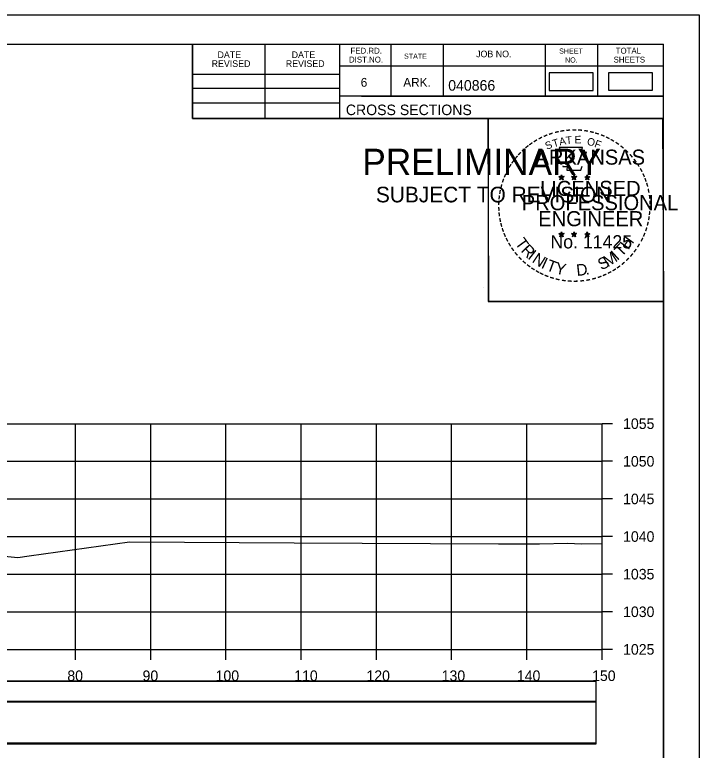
# Model space of a CAD drawing. Extents: x 1370565 to 1374448, y 301010 to 304637.
# Drawn here: x 1373440.7 to 1373531.7, y 302907.3 to 303005 of the extents above; entities that cross this region are included whole.
import ezdxf

# ---------------------------------------------------------------- set-up
doc = ezdxf.new("R2010")
doc.units = 0
for name, color, linetype in [('Default', 7, 'Continuous'), ('R_Axis', 7, 'Continuous'), ('R_Axis Annot', 7, 'Continuous'), ('R_Border', 7, 'Continuous'), ('R_Border PE', 7, 'Continuous'), ('R_Border Prem', 7, 'Continuous'), ('R_Drive', 7, 'Continuous'), ('R_Exist Surface', 7, 'Continuous'), ('R_Grid', 7, 'Continuous'), ('R_No Plot', 7, 'Continuous')]:
    doc.layers.add(name, color=color, linetype=linetype)

msp = doc.modelspace()

# ---------------------------------------------------------------- linework, layer by layer
at = {"layer": 'Default'}
for points in [[(1373511.808, 302994.967), (1373517.641, 302994.967), (1373517.641, 302997.277), (1373511.808, 302997.277)], [(1373219.605, 302913.703), (1373518.024, 302913.703), (1373518.024, 302916.409), (1373219.605, 302916.409)], [(1373219.605, 302908.125), (1373518.024, 302908.125), (1373518.024, 302913.648), (1373219.605, 302913.648)]]:
    msp.add_lwpolyline(points, close=True, dxfattribs=at)
at = {"layer": 'R_Axis'}
for p, q in [((1373518.814, 302920.664), (1373518.814, 302950.664)), ((1373520.214, 302950.664), (1373518.814, 302950.664)), ((1373520.214, 302945.664), (1373518.814, 302945.664)), ((1373520.214, 302940.664), (1373518.814, 302940.664)), ((1373520.214, 302935.664), (1373518.814, 302935.664)), ((1373520.214, 302930.664), (1373518.814, 302930.664)), ((1373520.214, 302925.664), (1373518.814, 302925.664)), ((1373218.814, 302920.664), (1373518.814, 302920.664)), ((1373448.814, 302919.264), (1373448.814, 302920.664)), ((1373458.814, 302919.264), (1373458.814, 302920.664)), ((1373468.814, 302919.264), (1373468.814, 302920.664)), ((1373478.814, 302919.264), (1373478.814, 302920.664)), ((1373488.814, 302919.264), (1373488.814, 302920.664)), ((1373498.814, 302919.264), (1373498.814, 302920.664)), ((1373508.814, 302919.264), (1373508.814, 302920.664)), ((1373518.814, 302919.264), (1373518.814, 302920.664)), ((1373520.214, 302920.664), (1373518.814, 302920.664))]:
    msp.add_line(p, q, dxfattribs=at)
at = {"layer": 'R_Border'}
for p, q in [((1373210.814, 303001.124), (1373526.994, 303001.124)), ((1373464.354, 302991.244), (1373464.354, 303001.124)), ((1373474.034, 302991.244), (1373474.034, 303001.124)), ((1373483.894, 303001.124), (1373483.894, 302991.244)), ((1373490.734, 303001.124), (1373490.734, 302994.184)), ((1373497.674, 303001.124), (1373497.674, 302994.184)), ((1373511.254, 303001.124), (1373511.254, 302994.184)), ((1373518.194, 303001.124), (1373518.194, 302994.184)), ((1373526.994, 302795.664), (1373526.994, 303001.124)), ((1373526.994, 302998.184), (1373483.894, 302998.184)), ((1373526.994, 302998.204), (1373526.994, 302998.204)), ((1373464.354, 302997.104), (1373483.894, 302997.104)), ((1373464.354, 302995.244), (1373483.894, 302995.244)), ((1373526.994, 302994.184), (1373483.894, 302994.184)), ((1373486.854, 302994.184), (1373526.994, 302994.184)), ((1373464.354, 302993.304), (1373483.894, 302993.304)), ((1373526.994, 302991.244), (1373464.354, 302991.244))]:
    msp.add_line(p, q, dxfattribs=at)
at = {"layer": 'R_Border PE'}
for p, q in [((1373513.079, 302983.499), (1373513.428, 302983.388)), ((1373513.079, 302983.499), (1373513.332, 302983.454)), ((1373513.079, 302983.499), (1373513.316, 302983.377)), ((1373513.212, 302983.091), (1373513.428, 302983.388)), ((1373513.212, 302983.091), (1373513.338, 302983.335)), ((1373513.212, 302983.091), (1373513.426, 302983.308)), ((1373513.428, 302983.753), (1373513.387, 302983.501)), ((1373513.641, 302983.091), (1373513.426, 302983.305)), ((1373513.428, 302983.388), (1373513.428, 302983.753)), ((1373513.428, 302983.753), (1373513.477, 302983.503)), ((1373513.775, 302983.499), (1373513.428, 302983.388)), ((1373513.641, 302983.091), (1373513.428, 302983.388)), ((1373513.775, 302983.499), (1373513.489, 302983.45)), ((1373513.641, 302983.091), (1373513.504, 302983.382)), ((1373513.775, 302983.499), (1373513.571, 302983.397)), ((1373514.749, 302983.499), (1373515.098, 302983.388)), ((1373514.749, 302983.499), (1373515.002, 302983.454)), ((1373514.749, 302983.499), (1373514.986, 302983.377)), ((1373514.882, 302983.091), (1373515.098, 302983.388)), ((1373514.882, 302983.091), (1373515.008, 302983.335)), ((1373514.882, 302983.091), (1373515.096, 302983.308)), ((1373515.098, 302983.753), (1373515.057, 302983.501)), ((1373515.311, 302983.091), (1373515.096, 302983.305)), ((1373515.098, 302983.388), (1373515.098, 302983.753)), ((1373515.098, 302983.753), (1373515.147, 302983.503)), ((1373515.445, 302983.499), (1373515.098, 302983.388)), ((1373515.311, 302983.091), (1373515.098, 302983.388)), ((1373515.445, 302983.499), (1373515.159, 302983.45)), ((1373515.311, 302983.091), (1373515.174, 302983.382)), ((1373515.445, 302983.499), (1373515.241, 302983.397)), ((1373516.513, 302983.487), (1373516.862, 302983.376)), ((1373516.513, 302983.487), (1373516.766, 302983.442)), ((1373516.513, 302983.487), (1373516.75, 302983.365)), ((1373516.646, 302983.079), (1373516.862, 302983.376)), ((1373516.646, 302983.079), (1373516.772, 302983.323)), ((1373516.646, 302983.079), (1373516.86, 302983.296)), ((1373516.862, 302983.741), (1373516.821, 302983.489)), ((1373517.075, 302983.079), (1373516.86, 302983.293)), ((1373516.862, 302983.376), (1373516.862, 302983.741)), ((1373516.862, 302983.741), (1373516.911, 302983.491)), ((1373517.209, 302983.487), (1373516.862, 302983.376)), ((1373517.075, 302983.079), (1373516.862, 302983.376)), ((1373517.209, 302983.487), (1373516.923, 302983.438)), ((1373517.075, 302983.079), (1373516.938, 302983.37)), ((1373517.209, 302983.487), (1373517.005, 302983.385)), ((1373513.075, 302975.926), (1373513.424, 302975.815)), ((1373513.075, 302975.926), (1373513.328, 302975.881)), ((1373513.075, 302975.926), (1373513.312, 302975.804)), ((1373513.208, 302975.518), (1373513.424, 302975.815)), ((1373513.208, 302975.518), (1373513.334, 302975.762)), ((1373513.208, 302975.518), (1373513.422, 302975.735)), ((1373513.424, 302976.18), (1373513.383, 302975.928)), ((1373513.637, 302975.518), (1373513.422, 302975.732)), ((1373513.424, 302975.815), (1373513.424, 302976.18)), ((1373513.424, 302976.18), (1373513.473, 302975.93)), ((1373513.771, 302975.926), (1373513.424, 302975.815)), ((1373513.637, 302975.518), (1373513.424, 302975.815)), ((1373513.771, 302975.926), (1373513.485, 302975.877)), ((1373513.637, 302975.518), (1373513.5, 302975.809)), ((1373513.771, 302975.926), (1373513.567, 302975.824)), ((1373514.744, 302975.926), (1373515.093, 302975.815)), ((1373514.744, 302975.926), (1373514.997, 302975.881)), ((1373514.744, 302975.926), (1373514.981, 302975.804)), ((1373514.877, 302975.518), (1373515.093, 302975.815)), ((1373514.877, 302975.518), (1373515.003, 302975.762)), ((1373514.877, 302975.518), (1373515.091, 302975.735)), ((1373515.093, 302976.18), (1373515.052, 302975.928)), ((1373515.306, 302975.518), (1373515.091, 302975.732)), ((1373515.093, 302975.815), (1373515.093, 302976.18)), ((1373515.093, 302976.18), (1373515.142, 302975.93)), ((1373515.44, 302975.926), (1373515.093, 302975.815)), ((1373515.306, 302975.518), (1373515.093, 302975.815)), ((1373515.44, 302975.926), (1373515.154, 302975.877)), ((1373515.306, 302975.518), (1373515.169, 302975.809)), ((1373515.44, 302975.926), (1373515.236, 302975.824)), ((1373516.511, 302975.916), (1373516.86, 302975.805)), ((1373516.511, 302975.916), (1373516.764, 302975.871)), ((1373516.511, 302975.916), (1373516.748, 302975.794)), ((1373516.644, 302975.508), (1373516.86, 302975.805)), ((1373516.644, 302975.508), (1373516.77, 302975.752)), ((1373516.644, 302975.508), (1373516.858, 302975.725)), ((1373516.86, 302976.17), (1373516.819, 302975.918)), ((1373517.073, 302975.508), (1373516.858, 302975.722)), ((1373516.86, 302975.805), (1373516.86, 302976.17)), ((1373516.86, 302976.17), (1373516.909, 302975.92)), ((1373517.207, 302975.916), (1373516.86, 302975.805)), ((1373517.073, 302975.508), (1373516.86, 302975.805)), ((1373517.207, 302975.916), (1373516.921, 302975.867)), ((1373517.073, 302975.508), (1373516.936, 302975.799)), ((1373517.207, 302975.916), (1373517.003, 302975.814))]:
    msp.add_line(p, q, dxfattribs=at)
for points in [[(1373513.12, 302987.377), (1373513.389, 302986.55)], [(1373516.631, 302986.455), (1373516.773, 302986.739), (1373516.088, 302986.715), (1373516.236, 302987.377), (1373513.12, 302987.377)], [(1373513.612, 302984.954), (1373513.612, 302984.867), (1373514.175, 302984.848), (1373514.121, 302984.375), (1373515.991, 302984.375), (1373516.192, 302984.911)], [(1373513.428, 302983.753), (1373513.641, 302983.091), (1373513.079, 302983.499), (1373513.775, 302983.499), (1373513.212, 302983.091), (1373513.428, 302983.753)], [(1373515.098, 302983.753), (1373515.311, 302983.091), (1373514.749, 302983.499), (1373515.445, 302983.499), (1373514.882, 302983.091), (1373515.098, 302983.753)], [(1373516.862, 302983.741), (1373517.075, 302983.079), (1373516.513, 302983.487), (1373517.209, 302983.487), (1373516.646, 302983.079), (1373516.862, 302983.741)], [(1373513.424, 302976.18), (1373513.637, 302975.518), (1373513.075, 302975.926), (1373513.771, 302975.926), (1373513.208, 302975.518), (1373513.424, 302976.18)], [(1373515.093, 302976.18), (1373515.306, 302975.518), (1373514.744, 302975.926), (1373515.44, 302975.926), (1373514.877, 302975.518), (1373515.093, 302976.18)], [(1373516.86, 302976.17), (1373517.073, 302975.508), (1373516.511, 302975.916), (1373517.207, 302975.916), (1373516.644, 302975.508), (1373516.86, 302976.17)]]:
    msp.add_lwpolyline(points, dxfattribs=at)
for centre, radius in [((1373513.427, 302983.388), 0.172), ((1373513.427, 302983.388), 0.145), ((1373513.427, 302983.388), 0.116), ((1373513.427, 302983.388), 0.0991), ((1373513.427, 302983.388), 0.0747), ((1373513.427, 302983.388), 0.0495), ((1373513.427, 302983.388), 0.0296), ((1373515.097, 302983.388), 0.172), ((1373515.097, 302983.388), 0.145), ((1373515.097, 302983.388), 0.116), ((1373515.097, 302983.388), 0.0991), ((1373515.097, 302983.388), 0.0747), ((1373515.097, 302983.388), 0.0495), ((1373515.097, 302983.388), 0.0296), ((1373516.861, 302983.376), 0.172), ((1373516.861, 302983.376), 0.145), ((1373516.861, 302983.376), 0.116), ((1373516.861, 302983.376), 0.0991), ((1373516.861, 302983.376), 0.0747), ((1373516.861, 302983.376), 0.0495), ((1373516.861, 302983.376), 0.0296), ((1373513.423, 302975.815), 0.172), ((1373513.423, 302975.815), 0.145), ((1373513.423, 302975.815), 0.116), ((1373513.423, 302975.815), 0.0991), ((1373513.423, 302975.815), 0.0747), ((1373513.423, 302975.815), 0.0495), ((1373513.423, 302975.815), 0.0296), ((1373515.092, 302975.815), 0.172), ((1373515.092, 302975.815), 0.145), ((1373515.092, 302975.815), 0.116), ((1373515.092, 302975.815), 0.0991), ((1373515.092, 302975.815), 0.0747), ((1373515.092, 302975.815), 0.0495), ((1373515.092, 302975.815), 0.0296), ((1373516.859, 302975.805), 0.172), ((1373516.859, 302975.805), 0.145), ((1373516.859, 302975.805), 0.116), ((1373516.859, 302975.805), 0.0991), ((1373516.859, 302975.805), 0.0747), ((1373516.859, 302975.805), 0.0495), ((1373516.859, 302975.805), 0.0296)]:
    msp.add_circle(centre, radius, dxfattribs=at)
at = {"layer": 'R_Drive'}
for points in [[(1373519.678, 302994.977), (1373525.511, 302994.977), (1373525.511, 302997.287), (1373519.678, 302997.287)], [(1373219.605, 302913.758), (1373518.024, 302913.758), (1373518.024, 302916.464), (1373219.605, 302916.464)], [(1373219.605, 302908.236), (1373518.024, 302908.236), (1373518.024, 302913.758), (1373219.605, 302913.758)]]:
    msp.add_lwpolyline(points, close=True, dxfattribs=at)
at = {"layer": 'R_Exist Surface'}
msp.add_lwpolyline([(1373295.897, 302935.209), (1373317.628, 302935.23), (1373320.318, 302935.147), (1373362.807, 302936.347), (1373371.847, 302936.582), (1373373.974, 302936.01), (1373386.19, 302932.68), (1373390.741, 302933.27), (1373403.062, 302934.774), (1373406.431, 302934.801), (1373413.69, 302934.857), (1373421.233, 302934.546), (1373423.278, 302934.459), (1373439.822, 302933.002), (1373441.145, 302932.879), (1373442.635, 302933.088), (1373456.008, 302934.961), (1373477.894, 302934.827), (1373505.041, 302934.68), (1373510.523, 302934.715), (1373514.262, 302934.801), (1373516.029, 302934.707), (1373518.814, 302934.728)], dxfattribs=at)
at = {"layer": 'R_Grid'}
for p, q in [((1373218.814, 302950.664), (1373518.814, 302950.664)), ((1373448.814, 302920.664), (1373448.814, 302950.664)), ((1373458.814, 302920.664), (1373458.814, 302950.664)), ((1373468.814, 302920.664), (1373468.814, 302950.664)), ((1373478.814, 302920.664), (1373478.814, 302950.664)), ((1373488.814, 302920.664), (1373488.814, 302950.664)), ((1373498.814, 302920.664), (1373498.814, 302950.664)), ((1373508.814, 302920.664), (1373508.814, 302950.664)), ((1373518.814, 302920.664), (1373518.814, 302950.664)), ((1373218.814, 302945.664), (1373518.814, 302945.664)), ((1373218.814, 302940.664), (1373518.814, 302940.664)), ((1373218.814, 302935.664), (1373518.814, 302935.664)), ((1373218.814, 302930.664), (1373518.814, 302930.664)), ((1373218.814, 302925.664), (1373518.814, 302925.664)), ((1373218.814, 302920.664), (1373518.814, 302920.664))]:
    msp.add_line(p, q, dxfattribs=at)
at = {"layer": 'R_No Plot'}
for p, q in [((1373198.414, 303005.019), (1373531.747, 303005.019)), ((1373503.029, 302968.789), (1373503.029, 302968.789))]:
    msp.add_line(p, q, dxfattribs=at)
for points in [[(1373198.407, 303005.019), (1373531.747, 303005.019), (1373531.747, 302791.681), (1373198.407, 302791.681)], [(1373444.734, 303001.124), (1373464.354, 303001.124), (1373464.354, 302991.244), (1373480.467, 302991.244), (1373503.666, 302991.244), (1373503.666, 302966.912), (1373526.994, 302966.912), (1373526.994, 302795.664), (1373210.814, 302795.664), (1373210.814, 303001.124)], [(1373503.666, 302991.244), (1373526.874, 302991.244), (1373526.994, 302966.912), (1373503.787, 302966.912)]]:
    msp.add_lwpolyline(points, close=True, dxfattribs=at)

# ---------------------------------------------------------------- texts
at = {"layer": 'R_Axis Annot'}
for s, p in [('1055', (1373521.614, 302949.964)), ('1050', (1373521.614, 302944.964)), ('1045', (1373521.614, 302939.964)), ('1040', (1373521.614, 302934.964)), ('1035', (1373521.614, 302929.964)), ('1030', (1373521.614, 302924.964)), ('1025', (1373521.614, 302919.964)), ('80', (1373447.729, 302916.464)), ('90', (1373457.729, 302916.464)), ('100', (1373467.442, 302916.464)), ('110', (1373477.894, 302916.464)), ('120', (1373487.497, 302916.464)), ('130', (1373497.497, 302916.464)), ('140', (1373507.497, 302916.464)), ('150', (1373517.497, 302916.464))]:
    msp.add_text(s, height=1.4, dxfattribs=at).set_placement(p)
at = {"layer": 'R_Border'}
for s, height, p in [('DATE', 0.8792, (1373467.692, 302999.26)), ('DATE', 0.8792, (1373477.552, 302999.26)), ('FED.RD.', 0.7819, (1373485.374, 302999.844)), ('STATE', 0.684, (1373492.494, 302999.164)), ('JOB NO.', 0.8792, (1373502.074, 302999.364)), ('SHEET', 0.684, (1373513.114, 302999.844)), ('TOTAL', 0.7819, (1373520.634, 302999.844)), ('REVISED', 0.8792, (1373466.912, 302998.08)), ('REVISED', 0.8792, (1373476.772, 302998.08)), ('DIST.NO.', 0.7819, (1373485.174, 302998.664)), ('NO.', 0.684, (1373513.894, 302998.664)), ('SHEETS', 0.7819, (1373520.354, 302998.664)), ('6', 1.172, (1373486.734, 302995.444)), ('ARK.', 1.1723, (1373492.394, 302995.444)), ('040866', 1.4, (1373498.37, 302994.924)), ('CROSS SECTIONS', 1.4, (1373484.758, 302991.674))]:
    msp.add_text(s, height=height, rotation=360, dxfattribs=at).set_placement(p)
at = {"layer": 'R_Border PE'}
for s, height, rotation, p in [('-', 1.6, 24.30721, (1373511.234, 302988.235)), ('-', 1.6, 19.17608, (1373511.868, 302988.504)), ('-', 1.6, 13.63015, (1373512.618, 302988.745)), ('-', 1.6, 10.21935, (1373513.296, 302988.907)), ('-', 1.6, 5.89682, (1373514.025, 302989.017)), ('-', 1.6, 0.18623, (1373514.797, 302989.089)), ('-', 1.6, 357.74304, (1373515.52, 302989.076)), ('-', 1.6, 352.16172, (1373516.264, 302989.02)), ('-', 1.6, 347.20489, (1373516.983, 302988.906)), ('-', 1.6, 342.3362, (1373517.618, 302988.751)), ('-', 1.6, 337.85509, (1373518.353, 302988.528)), ('-', 1.6, 36.23174, (1373509.426, 302987.153)), ('-', 1.6, 34.06357, (1373510.004, 302987.548)), ('-', 1.6, 28.79182, (1373510.601, 302987.918)), ('S', 1, 21.59401, (1373511.475, 302987.055)), ('T', 1, 16.4036, (1373512.389, 302987.386)), ('A', 1, 11.21318, (1373513.215, 302987.637)), ('T', 1, 6.02276, (1373514.064, 302987.803)), ('E', 1, 0.83234, (1373515.169, 302987.913)), ('O', 1, 350.4515, (1373516.773, 302987.703)), ('F', 1, 340.07066, (1373517.727, 302987.475)), ('-', 1.6, 334.12109, (1373518.984, 302988.257)), ('-', 1.6, 329.64089, (1373519.563, 302987.974)), ('-', 1.6, 325.86266, (1373520.206, 302987.613)), ('-', 1.6, 42.96224, (1373508.517, 302986.358)), ('-', 1.6, 38.95066, (1373508.95, 302986.775)), ('ARKANSAS', 2, 360, (1373509.973, 302985.089)), ('-', 1.6, 320.52971, (1373520.816, 302987.187)), ('-', 1.6, 315.57859, (1373521.415, 302986.699)), ('-', 1.6, 50.61417, (1373507.666, 302985.394)), ('-', 1.6, 48.42305, (1373508.069, 302985.88)), ('-', 1.6, 309.87973, (1373521.984, 302986.149)), ('-', 1.6, 58.07063, (1373506.928, 302984.3)), ('-', 1.6, 54.23247, (1373507.253, 302984.827)), ('-', 1.6, 306.65218, (1373522.509, 302985.547)), ('-', 1.4, 303.67529, (1373522.995, 302984.979)), ('-', 1.6, 62.87135, (1373506.615, 302983.686)), ('-', 1.6, 299.66835, (1373523.314, 302984.372)), ('-', 1.6, 72.39447, (1373506.137, 302982.445)), ('-', 1.6, 67.77427, (1373506.356, 302983.075)), ('DWB', 0.01, 360, (1373513.415, 302983.383)), ('DWB', 0.01, 360, (1373515.085, 302983.383)), ('DWB', 0.01, 360, (1373516.849, 302983.372)), ('-', 1.6, 294.66279, (1373523.638, 302983.76)), ('-', 1.6, 290.57283, (1373523.895, 302983.183)), ('-', 1.6, 75.46096, (1373505.94, 302981.731)), ('LICENSED', 2, 360, (1373510.571, 302980.94)), ('-', 1.6, 285.12326, (1373524.129, 302982.603)), ('-', 1.6, 81.20126, (1373505.808, 302981.018)), ('-', 1.6, 280.54934, (1373524.329, 302981.861)), ('-', 1.6, 89.06224, (1373505.707, 302979.626)), ('-', 1.6, 85.18634, (1373505.732, 302980.327)), ('PROFESSIONAL', 2, 360, (1373508.147, 302979.036)), ('-', 1.6, 276.59616, (1373524.491, 302981.093)), ('-', 1.6, 274.33011, (1373524.551, 302980.371)), ('-', 1.6, 94.19588, (1373505.742, 302978.901)), ('-', 1.6, 269.94067, (1373524.585, 302979.739)), ('-', 1.6, 98.94793, (1373505.814, 302978.234)), ('ENGINEER', 2, 360, (1373510.334, 302976.911)), ('-', 1.6, 260.99529, (1373524.495, 302978.419)), ('-', 1.6, 263.5172, (1373524.566, 302979.073)), ('-', 1.6, 101.71495, (1373505.949, 302977.501)), ('-', 1.6, 105.45785, (1373506.111, 302976.906)), ('-', 1.6, 255.7626, (1373524.385, 302977.741)), ('-', 1.6, 109.08742, (1373506.326, 302976.275)), ('-', 1.6, 252.86809, (1373524.204, 302977.021)), ('-', 1.6, 114.06432, (1373506.58, 302975.679)), ('-', 1.6, 115.72885, (1373506.885, 302975.061)), ('T', 1.54, 306.04056, (1373507.184, 302974.654)), ('No. 11425', 1.757, 360, (1373511.962, 302973.96)), ('DWB', 0.01, 360, (1373513.411, 302975.81)), ('DWB', 0.01, 360, (1373515.08, 302975.811)), ('DWB', 0.01, 360, (1373516.847, 302975.801)), ('H', 1.54, 54.60883, (1373522.304, 302973.689)), ('-', 1.6, 244.61971, (1373523.719, 302975.719)), ('-', 1.6, 247.88866, (1373523.981, 302976.348)), ('-', 1.6, 120.44712, (1373507.242, 302974.475)), ('R', 1.54, 314.00497, (1373507.946, 302973.606)), ('T', 1.54, 46.64442, (1373521.415, 302972.746)), ('-', 1.6, 239.07125, (1373523.325, 302974.967)), ('-', 1.6, 125.89344, (1373507.645, 302973.914)), ('-', 1.6, 130.71812, (1373508.107, 302973.362)), ('I', 1.54, 321.96938, (1373508.847, 302972.674)), ('N', 1.54, 326.50021, (1373509.414, 302972.202)), ('M', 1.54, 32.65632, (1373519.569, 302971.421)), ('I', 1.54, 42.11359, (1373520.853, 302972.268)), ('-', 1.6, 231.25377, (1373522.493, 302973.748)), ('-', 1.6, 233.84524, (1373522.923, 302974.314)), ('-', 1.6, 134.22381, (1373508.624, 302972.817)), ('-', 1.6, 138.93382, (1373509.149, 302972.353)), ('I', 1.54, 335.36034, (1373510.622, 302971.416)), ('T', 1.54, 339.89117, (1373511.283, 302971.089)), ('S', 1.54, 26.9312, (1373518.73, 302971.015)), ('-', 1.6, 225.76533, (1373522.014, 302973.184)), ('-', 1.6, 144.64634, (1373509.705, 302971.947)), ('-', 1.6, 148.08978, (1373510.266, 302971.576)), ('Y', 1.54, 347.85558, (1373512.5, 302970.643)), ('D', 1.54, 6.39691, (1373515.485, 302970.285)), ('-', 1.6, 215.73633, (1373520.943, 302972.203)), ('-', 1.6, 221.08509, (1373521.492, 302972.675)), ('-', 1.6, 151.57039, (1373510.845, 302971.251)), ('-', 1.6, 154.60019, (1373511.367, 302971.004)), ('-', 1.6, 158.56121, (1373511.991, 302970.75)), ('.', 1.54, 13.76417, (1373516.677, 302970.412)), ('-', 1.6, 204.25161, (1373519.227, 302971.151)), ('-', 1.6, 207.35684, (1373519.851, 302971.47)), ('-', 1.6, 212.24909, (1373520.409, 302971.816)), ('-', 1.6, 162.79826, (1373512.678, 302970.537)), ('-', 1.6, 167.55551, (1373513.393, 302970.373)), ('-', 1.6, 173.11546, (1373514.165, 302970.263)), ('-', 1.6, 176.51827, (1373514.913, 302970.21)), ('-', 1.6, 181.59176, (1373515.657, 302970.229)), ('-', 1.6, 185.81666, (1373516.466, 302970.305)), ('-', 1.6, 191.28576, (1373517.202, 302970.437)), ('-', 1.6, 195.47429, (1373517.931, 302970.636)), ('-', 1.6, 200.71842, (1373518.608, 302970.878))]:
    msp.add_text(s, height=height, rotation=rotation, dxfattribs=at).set_placement(p)
at = {"layer": 'R_Border Prem'}
for s, height, p in [('PRELIMINARY', 3.5, (1373486.946, 302983.707)), ('DWB', 0.01, (1373487.692, 302985.557)), ('SUBJECT TO REVISION', 2.07511, (1373488.755, 302980.078))]:
    msp.add_text(s, height=height, rotation=360, dxfattribs=at).set_placement(p)

doc.saveas('drawing.dxf')
